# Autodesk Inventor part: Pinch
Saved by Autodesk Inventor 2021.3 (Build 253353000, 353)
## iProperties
Created: 2022-09
Part Number: Pinch
Material: Generic
Document SubType Name: Modeling
Designer: Administrator
Density: 1 g/cm^3
Appearance: Default
Title: Pinch v3
Author: Administrator
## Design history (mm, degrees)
feature "Body1"
feature "Socket Body" [Body]
feature "Shade Ring" [Body]
feature "Shade Ring +Collar" [Body]
feature "Socket" [Body]
feature "Body1 (1)"
feature "Metal Strain Relief" [Body]
feature "Fabric Cord (1)" [Body]
feature "Stem (Threaded)" [Body]
feature "Cap (Threaded)" [Body]
feature "T9-Bulb" [Body]
body "Solid1"
body "Solid2"
body "Solid3"
body "Solid4"
body "Solid5"
body "Solid6"
body "Solid7"
body "Solid8"
body "Solid9"
body "Solid10"
body "Solid11"
